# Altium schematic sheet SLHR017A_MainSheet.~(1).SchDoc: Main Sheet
size 431 x 279 mm; Date: Not shown in title block; ApprovedBy: Not shown in title block; CheckedBy: Not shown in title block; Author: Not shown in title block; CompanyName: Not shown in title block; DrawnBy: Kirby Kruckmeyer; Engineer: Not shown in title block; Organization: Not shown in title block; Address1: Not shown in title block; Address2: Not shown in title block; Address3: Not shown in title block; Address4: Not shown in title block; DocumentNumber: 1; Revision: Use project parameter SCH_Rev; SheetNumber: 1; SheetTotal: 2; PageSetup: Record=PageOptions¦CenterHorizontal=True¦CenterVertical=True¦PrintScale=1.00¦XCorrection=1.00¦YCorrection=1.00¦PrintKind=0¦BorderSize=5000000¦LeftOffset=0¦BottomOffset=0¦Orientation=2¦PaperLength=1000¦PaperWidth=1000¦Scale=100¦PaperSource=15¦PrintQuality=600¦MediaType=1¦DitherType=10¦PaperKind=Letter¦PrintScaleMode=1
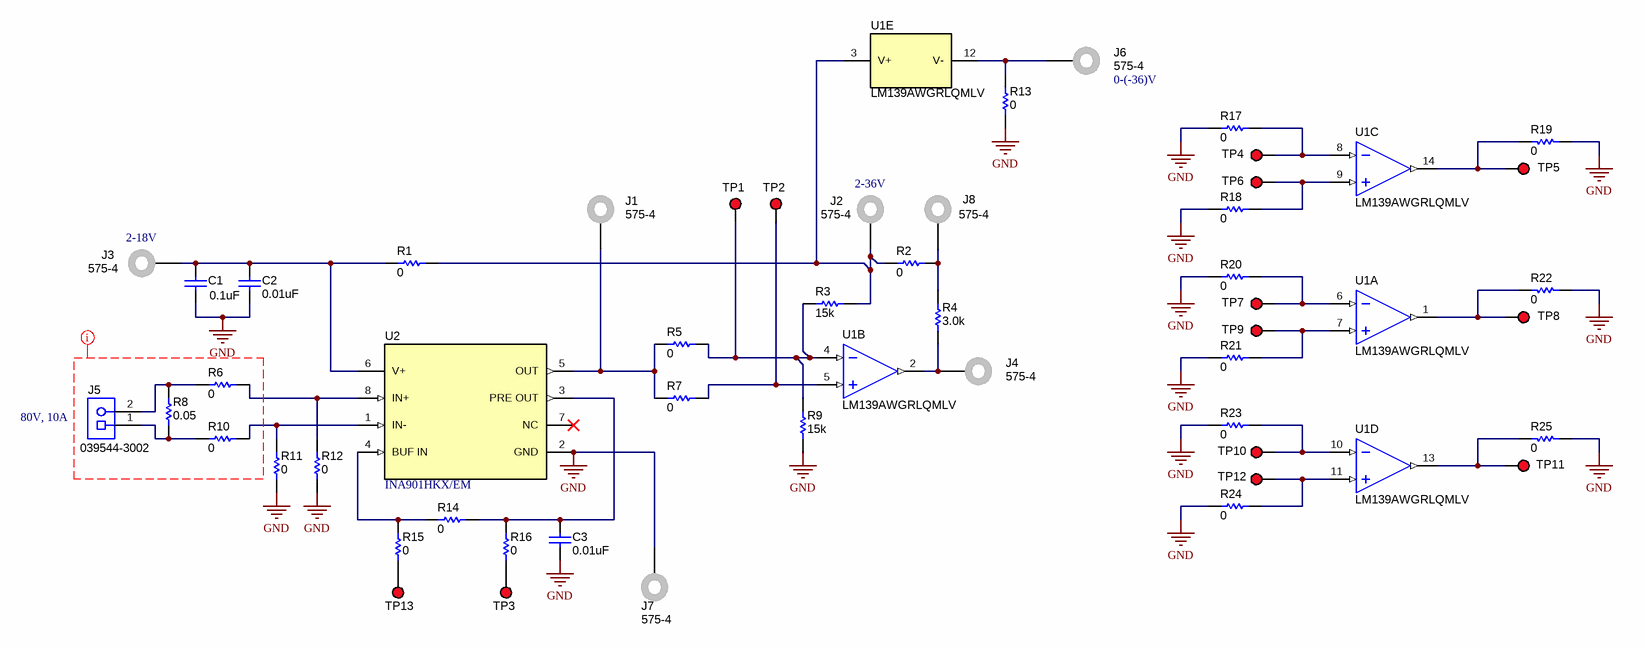
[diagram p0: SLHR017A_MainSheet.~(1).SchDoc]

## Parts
C1  ValueDisplayed: 0.1uF  [0805_HV]  (hidden comment: C0805C104K1RACTU)
C2  ValueDisplayed: 0.01uF  [0805_HV]  (hidden comment: C0805C103F1GACTU)
C3  ValueDisplayed: 0.01uF  [0805_HV]  (hidden comment: C0805C103F1GACTU)
J1  575-4  [Keystone_575-4]
J2  575-4  [Keystone_575-4]
J3  575-4  [Keystone_575-4]
J4  575-4  [Keystone_575-4]
J5  039544-3002  [Molex_039544-3002]
J6  575-4  [Keystone_575-4]
J7  575-4  [Keystone_575-4]
J8  575-4  [Keystone_575-4]
R1  ValueDisplayed: 0  [0805_HV]  (hidden comment: ERJ-6GEY0R00V)
R2  ValueDisplayed: 0  [0805_HV]  (hidden comment: ERJ-6GEY0R00V)
R3  ValueDisplayed: 15k  [0805_HV]  (hidden comment: ERJ-6GEYJ153V)
R4  ValueDisplayed: 3.0k  [0805_HV]  (hidden comment: ERJ-6GEYJ302V)
R5  ValueDisplayed: 0  [0805_HV]  (hidden comment: ERJ-6GEY0R00V)
R6  ValueDisplayed: 0  [0805_HV]  (hidden comment: ERJ-6GEY0R00V)
R7  ValueDisplayed: 0  [0805_HV]  (hidden comment: ERJ-6GEY0R00V)
R8  ValueDisplayed: 0.05  [4320]  (hidden comment: KRL11050-C-R050-F-T1)
R9  ValueDisplayed: 15k  [0805_HV]  (hidden comment: ERJ-6GEYJ153V)
R10  ValueDisplayed: 0  [0805_HV]  (hidden comment: ERJ-6GEY0R00V)
R11  ValueDisplayed: 0  [0805_HV]  (hidden comment: ERJ-6GEY0R00V)
R12  ValueDisplayed: 0  [0805_HV]  (hidden comment: ERJ-6GEY0R00V)
R13  ValueDisplayed: 0  [0805_HV]  (hidden comment: ERJ-6GEY0R00V)
R14  ValueDisplayed: 0  [0805_HV]  (hidden comment: ERJ-6GEY0R00V)
R15  ValueDisplayed: 0  [0805_HV]  (hidden comment: ERJ-6GEY0R00V)
R16  ValueDisplayed: 0  [0805_HV]  (hidden comment: ERJ-6GEY0R00V)
R17  ValueDisplayed: 0  [0805_HV]  (hidden comment: ERJ-6GEY0R00V)
R18  ValueDisplayed: 0  [0805_HV]  (hidden comment: ERJ-6GEY0R00V)
R19  ValueDisplayed: 0  [0805_HV]  (hidden comment: ERJ-6GEY0R00V)
R20  ValueDisplayed: 0  [0805_HV]  (hidden comment: ERJ-6GEY0R00V)
R21  ValueDisplayed: 0  [0805_HV]  (hidden comment: ERJ-6GEY0R00V)
R22  ValueDisplayed: 0  [0805_HV]  (hidden comment: ERJ-6GEY0R00V)
R23  ValueDisplayed: 0  [0805_HV]  (hidden comment: ERJ-6GEY0R00V)
R24  ValueDisplayed: 0  [0805_HV]  (hidden comment: ERJ-6GEY0R00V)
R25  ValueDisplayed: 0  [0805_HV]  (hidden comment: ERJ-6GEY0R00V)
TP1  5010  [Keystone5010]  (value not drawn)
TP2  5010  [Keystone5010]  (value not drawn)
TP3  5010  [Keystone5010]  (value not drawn)
TP4  5010  [Keystone5010]  (value not drawn)
TP5  5010  [Keystone5010]  (value not drawn)
TP6  5010  [Keystone5010]  (value not drawn)
TP7  5010  [Keystone5010]  (value not drawn)
TP8  5010  [Keystone5010]  (value not drawn)
TP9  5010  [Keystone5010]  (value not drawn)
TP10  5010  [Keystone5010]  (value not drawn)
TP11  5010  [Keystone5010]  (value not drawn)
TP12  5010  [Keystone5010]  (value not drawn)
TP13  5010  [Keystone5010]  (value not drawn)
U1  LM139AWGRLQMLV  [NAC0014A_N]  (parts A,B,C,D,E of 5)
U2  INA901HKX/EM  [HKX0008A_Custom_B]

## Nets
GND: C1.2 C2.2 C3.2 J7.1 R9.1 R11.1 R12.1 R13.1 R17.1 R18.1 R19.1 R20.1 R21.1 R22.1 R23.1 R24.1 R25.1 U2.2(GND)
NetC1_1: C1.1 C2.1 J3.1 R1.2 U2.6(V+)
NetC3_1: C3.1 R14.2 R16.2 U2.3(PRE_OUT)
NetJ1_1: J1.1 R5.1 R7.1 U2.5(OUT)
NetJ2_1: J2.1 R1.1 R2.1 R3.2 U1.3(V+)
NetJ4_1: J4.1 R4.1 U1.2(OUT1)
NetJ5_1: J5.1 R8.1 R10.1
NetJ5_2: J5.2 R6.1 R8.2
NetJ6_1: J6.1 R13.2 U1.12(V-)
NetJ8_1: J8.1 R2.2 R4.2
NetR3_1: R3.1 R5.2 R9.2 TP1.1 U1.4(-IN1)
NetR6_2: R6.2 R12.2 U2.8(IN+)
NetR7_2: R7.2 TP2.1 U1.5(+IN1)
NetR10_2: R10.2 R11.2 U2.1(IN-)
NetR14_1: R14.1 R15.2 U2.4(BUF_IN)
NetR15_1: R15.1 TP13.1
NetR16_1: R16.1 TP3.1
NetR17_2: R17.2 TP4.1 U1.8(-IN3)
NetR18_2: R18.2 TP6.1 U1.9(+IN3)
NetR19_2: R19.2 TP5.1 U1.14(OUT3)
NetR20_2: R20.2 TP7.1 U1.6(-IN2)
NetR21_2: R21.2 TP9.1 U1.7(+IN2)
NetR22_2: R22.2 TP8.1 U1.1(OUT2)
NetR23_2: R23.2 TP10.1 U1.10(-IN4)
NetR24_2: R24.2 TP12.1 U1.11(+IN4)
NetR25_2: R25.2 TP11.1 U1.13(OUT4)

Not connected (* = marked no-connect by the designer): U2 7(NC)*

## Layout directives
net class HV_Net: (no net found under the mark)

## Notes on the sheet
- (near J6) 0-(-36)V
- (near J2) 2-36V
- (near J3) 2-18V
- (near J5) 80V, 10A

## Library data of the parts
C1 = CMP-0007722-2: CAP, CERM, 0.1 uF, 100 V, +/- 10%, X7R, 0805; Manufacturer: Kemet; TaMin_C: -55°C; ESR_ohm: 0.064; Polarized: N; SizeAreaWB_mm2: 6.75; Value1: 0.064 ohm; U/M: EA; Value: 0.1uF; TaMax_C: 125°C; SizeZ_mm: 1.45; SizeX_mm: 2; SizeY_mm: 1.25; Cap_Case: 0805; Value2: 100V; SizeArea_mm2: 2.5; Cap_F: 100nF; IRMS_A: 1.64A; AEC Category: Q200
C2 C3 = CMP-0007716-2: CAP, CERM, 0.01 uF, 100 V, +/- 1%, C0G/NP0, 0805; Manufacturer: Kemet; TaMin_C: -55°C; Polarized: N; SizeAreaWB_mm2: 6.75; Value1: Unknown; U/M: EA; Value: 0.01uF; TaMax_C: 125°C; SizeZ_mm: 1.45; SizeX_mm: 2; SizeY_mm: 1.25; Cap_Case: 0805; Value2: 100V; SizeArea_mm2: 2.5; Cap_F: 10nF; AEC Category: Q200
J1-J4 J6-J8 = CMP-0055165-2: Standard Banana Jack, Uninsulated, 5.5mm; Manufacturer: Keystone; CT: TRUE; Green_REACh: Passed; CNHeader: FALSE; Green_Lifecycle: Active
J5 = CMP-0055345-1: Terminal Block, 5.08mm, 2x1, TH; Manufacturer: Molex; CNHeader: FALSE; Current_A: 15A; Gender: Female; Voltage_V: 300V; Row_Count: 1; Pitch_mm: 5.08; ContactFinish: Tin; CT: TRUE; Cert_UL: Y
R1 R2 R5-R7 R10-R25 = CMP-0020616-3: RES, 0, 5%, 0.125 W, AEC-Q200 Grade 0, 0805; Manufacturer: Panasonic; Power_W: 125mW; TempCo: 600 ppm/C; Value_Code: 0000; Value: 0; EIA_Code: E24; SizeX_mm: 2; SizeY_mm: 1.25; SizeZ_mm: 1.45; Value2: 0.125W; SizeArea_mm2: 2.5; AEC Qualified: Y; VDC_V: 150V; AEC Category: Q200; SizeAreaWB_mm2: 6.75
R3 R9 = CMP-0020646-3: RES, 15 k, 5%, 0.125 W, AEC-Q200 Grade 0, 0805; Manufacturer: Panasonic; Power_W: 125mW; TempCo: 200 ppm/C; Value_Code: 15k0; Value: 15k; EIA_Code: E24; SizeX_mm: 2; SizeY_mm: 1.25; SizeZ_mm: 1.45; Value2: 0.125W; SizeArea_mm2: 2.5; AEC Qualified: Y; VDC_V: 150V; AEC Category: Q200; AEC Grade: 0; SizeAreaWB_mm2: 6.75
R4 = CMP-0020698-3: RES, 3.0 k, 5%, 0.125 W, AEC-Q200 Grade 0, 0805; Manufacturer: Panasonic; Power_W: 125mW; TempCo: 200 ppm/C; Value_Code: 3k00; Value: 3.0k; EIA_Code: E24; Res_ohm: 3k; SizeX_mm: 2; SizeY_mm: 1.25; SizeZ_mm: 1.45; Value2: 0.125W; SizeArea_mm2: 2.5; AEC Qualified: Y; VDC_V: 150V; AEC Category: Q200; AEC Grade: 0; SizeAreaWB_mm2: 6.75
R8 = CMP-0015099-2: RES, 0.05, 1%, 6 W, 4320_WIDE; Manufacturer: Susumu Co Ltd; Power_W: 6W; TempCo: 50 ppm/C; Value_Code: R050; U/M: EA; Value: 0.05; EIA_Code: E96; AEC Category: Q200
TP1-TP13 = CMP-0055147-1: Test Point, Multipurpose, Red, TH; Manufacturer: Keystone; CNHeader: FALSE; Green_Lifecycle: Active; Green_REACh: Passed; ContactFinish: Silver; CT: TRUE
U1 = CMP-0068426-2: Low Power Low Offset Voltage Quad Comparator, NAC0014A (CFP-14); Manufacturer: Texas Instruments; AEC Qualified: N; SizeX_mm: 10.41; SizeArea_mm2: 103.16; SizeZ_mm: 2.03; Rating: Space; CompType: Amplifiers; AEC Category: Q200; SizeAreaWB_mm2: 147.8; SizeY_mm: 9.91
U2 = CMP-0081563-2: Voltage Output, Unidirectional Measurement Current-Shunt Monitor, HKX0008A (CFP-8); Manufacturer: Texas Instruments; SizeZ_mm: 2.8; Rating: Space; AEC Category: Q200; CompType: IC; AEC Qualified: N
